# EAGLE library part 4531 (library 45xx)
12-bit PARITY TREE
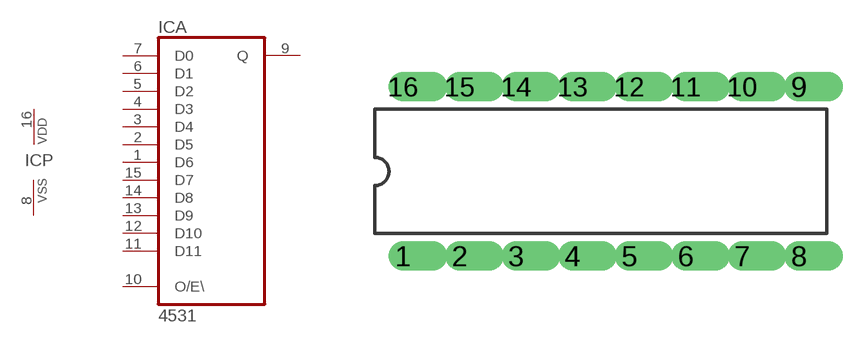
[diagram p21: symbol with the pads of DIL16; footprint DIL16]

Designator prefix IC; gates A=4531 P=PWRN

## 4531N  [DIL16]
1  A:D6  in
2  A:D5  in
3  A:D4  in
4  A:D3  in
5  A:D2  in
6  A:D1  in
7  A:D0  in
8  P:VSS  pwr
9  A:Q  out
10  A:O/E\  in
11  A:D11  in
12  A:D10  in
13  A:D9  in
14  A:D8  in
15  A:D7  in
16  P:VDD  pwr

## Footprint DIL16 (pad centres in mm)
Dual In Line
drill 0.813 offset: 1 -8.89,-3.81; 2 -6.35,-3.81; 3 -3.81,-3.81; 4 -1.27,-3.81; 5 1.27,-3.81; 6 3.81,-3.81; 7 6.35,-3.81; 8 8.89,-3.81; 9 8.89,3.81; 10 6.35,3.81; 11 3.81,3.81; 12 1.27,3.81; 13 -1.27,3.81; 14 -3.81,3.81; 15 -6.35,3.81; 16 -8.89,3.81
